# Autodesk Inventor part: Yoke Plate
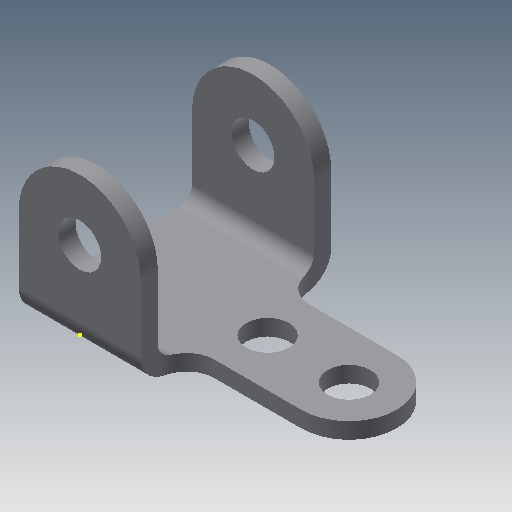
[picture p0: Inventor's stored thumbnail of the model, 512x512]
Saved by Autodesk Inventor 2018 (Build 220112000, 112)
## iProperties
Created: 2011-04
Part Number: Yoke Plate
Material: Generic
Document SubType Name: Modeling
Designer: Dell
Density: 1 g/cm^3
Appearance: Default
Author: Dell
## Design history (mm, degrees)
sketch "Sketch1"
  geometry: 1 further point
sketch "Sketch2"
  geometry: L1 (28.5, 36.5)-(28.5, -7.5); L2 (-28.5, -7.5)-(28.5, -7.5); L3 (-28.5, 36.5)-(-28.5, -7.5); C1 r 10 at (0, 36.5); A1 r 28.5 centre (0, 36.5) between (28.5, 36.5) and (-28.5, 36.5); 2 further points
  constraints: 6 end point, 2 centre point, 2 point on circle, 2 tangent, 2 vertical, 1 coincident, 1 perpendicular, 1 other
  dimensions: "d0" = 57 distance of L2.start L1.end; "d1" = 36.5 distance of point (0, 0) C1.centre; "d2" = 28.5 distance from line of L1 point (0, 0); "d3" = 20 diameter of C1; "d24" = 7.5 distance from line of point (0, 0) L2
extrude "Extrusion1" new body sketch "Sketch2" distance "d4" = 89; taper "d5" = 0 deg
sketch "Sketch3"
  geometry: L1 (44, 89)-(0, 89) reference; L2 (-28.588, 8)-(36.5, 8); L3 (36.5, 8)-(36.5, 81); L4 (36.5, 81)-(-28.588, 81); L5 (-28.588, 8)-(-28.588, 81); L6 (-28.5, 89)-(0, 89) reference; 3 further points
  constraints: 8 end point, 1 perpendicular
  dimensions: "d6" = 73 distance of L2.start L4.end; "d9" = 8 distance between parallel lines of L1 L4
extrude "Extrusion2" cut sketch "Sketch3" distance "d10" = 89; taper "d11" = 0 deg
sketch "Sketch4"
  geometry: L1 (0, 58.08)-(53.5, 58.08); L2 (53.5, 13.58)-(0, 13.58); L3 (0, 13.58)-(0, 58.08); L4 (0, 35.83)-(93.365, 35.83); L5 (0, 73)-(0, 0) reference; C1 r 10 at (53.5, 35.83); C2 r 10 at (15.5, 35.83); A1 r 22.25 centre (53.5, 35.83) between (53.5, 13.58) and (53.5, 58.08); 1 further point
  constraints: 8 end point, 3 centre point, 2 horizontal, 2 point on circle, 1 coincident, 1 collinear, 1 equal radius, 1 horizontal alignment, 1 parallel, 1 perpendicular, 1 point on line, 1 tangent
  dimensions: "d12" = 44.5 diameter of A1; "d13" = 44.5 distance between parallel lines of L2 L1; "d14" = 20 diameter of C1; "d15" = 38 distance of A1.centre C2.centre; "d23" = 15.5 distance from line of C2.centre L3
extrude "Extrusion3" join sketch "Sketch4" stored distance "d16" = 89; taper "d17" = 0 deg
fillet "Fillet1" dims "d18" = 12.7
fillet "Fillet2" dims "d19" = 6.35
fillet "Fillet3" dims "d20" = 12.75
body "Solid1"
